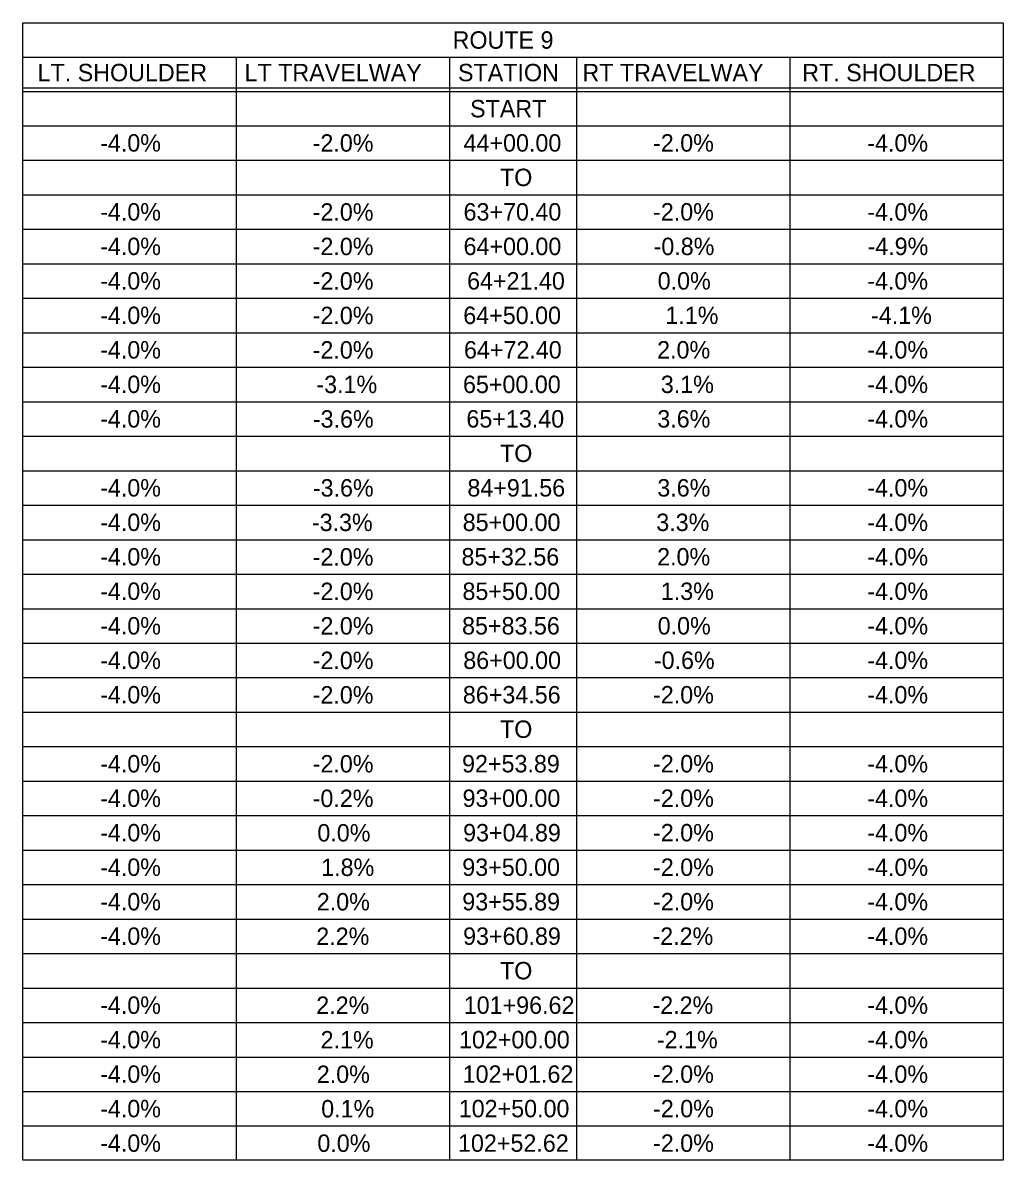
# Model space of a CAD drawing. Extents: x -15319374 to 1762012, y 465773 to 3693661.
# Drawn here: x -15318626.1 to -15318457.2, y 3691771.6 to 3691967.6 of the extents above; entities that cross this region are included whole.
import ezdxf

# ---------------------------------------------------------------- set-up
doc = ezdxf.new("R2010")
doc.units = 0
doc.layers.add('BORDER', color=7, linetype='Continuous')
doc.layers.add('DIMENSIONS', color=7, linetype='Continuous')

msp = doc.modelspace()

# ---------------------------------------------------------------- linework, layer by layer
at = {"layer": 'BORDER'}
for p, q in [((-15318589.38, 3691961.63), (-15318589.38, 3691771.58)), ((-15318552.61, 3691961.63), (-15318552.61, 3691771.58)), ((-15318530.73, 3691961.63), (-15318530.73, 3691771.58)), ((-15318493.97, 3691961.63), (-15318493.97, 3691771.58)), ((-15318626.15, 3691956.35), (-15318457.2, 3691956.35)), ((-15318626.15, 3691955.75), (-15318457.2, 3691955.75)), ((-15318626.15, 3691949.81), (-15318457.2, 3691949.81)), ((-15318626.15, 3691949.81), (-15318457.2, 3691949.81)), ((-15318626.15, 3691949.81), (-15318457.2, 3691949.81)), ((-15318626.15, 3691943.87), (-15318457.2, 3691943.87)), ((-15318626.15, 3691937.92), (-15318457.2, 3691937.92)), ((-15318626.15, 3691931.98), (-15318457.2, 3691931.98)), ((-15318626.15, 3691926.04), (-15318457.2, 3691926.04)), ((-15318626.15, 3691920.1), (-15318457.2, 3691920.1)), ((-15318626.15, 3691914.15), (-15318457.2, 3691914.15)), ((-15318626.15, 3691908.21), (-15318457.2, 3691908.21)), ((-15318626.15, 3691902.27), (-15318457.2, 3691902.27)), ((-15318626.15, 3691896.33), (-15318457.2, 3691896.33)), ((-15318626.15, 3691890.38), (-15318457.2, 3691890.38)), ((-15318626.15, 3691884.44), (-15318457.2, 3691884.44)), ((-15318626.15, 3691878.5), (-15318457.2, 3691878.5)), ((-15318626.15, 3691872.56), (-15318457.2, 3691872.56)), ((-15318626.15, 3691866.61), (-15318457.2, 3691866.61)), ((-15318626.15, 3691860.67), (-15318457.2, 3691860.67)), ((-15318626.15, 3691854.73), (-15318457.2, 3691854.73)), ((-15318626.15, 3691848.78), (-15318457.2, 3691848.78)), ((-15318626.15, 3691842.84), (-15318457.2, 3691842.84)), ((-15318626.15, 3691836.9), (-15318457.2, 3691836.9)), ((-15318626.15, 3691830.96), (-15318457.2, 3691830.96)), ((-15318626.15, 3691825.01), (-15318457.2, 3691825.01)), ((-15318626.15, 3691819.07), (-15318457.2, 3691819.07)), ((-15318626.15, 3691813.13), (-15318457.2, 3691813.13)), ((-15318626.15, 3691807.19), (-15318457.2, 3691807.19)), ((-15318626.15, 3691801.24), (-15318457.2, 3691801.24)), ((-15318626.15, 3691795.3), (-15318457.2, 3691795.3)), ((-15318626.15, 3691789.36), (-15318457.2, 3691789.36)), ((-15318626.15, 3691783.41), (-15318457.2, 3691783.41)), ((-15318626.15, 3691777.49), (-15318457.2, 3691777.49))]:
    msp.add_line(p, q, dxfattribs=at)
msp.add_lwpolyline([(-15318626.15, 3691961.63), (-15318626.15, 3691967.57), (-15318457.2, 3691967.57), (-15318457.2, 3691961.63)], dxfattribs=at)
msp.add_lwpolyline([(-15318626.15, 3691961.63), (-15318457.2, 3691961.63), (-15318457.2, 3691771.58), (-15318626.15, 3691771.58)], close=True, dxfattribs=at)

# ---------------------------------------------------------------- texts
at = {"layer": 'DIMENSIONS'}
for s, p in [('ROUTE 9', (-15318552.08, 3691963.1)), ('LT. SHOULDER', (-15318623.59, 3691957.49)), ('LT TRAVELWAY', (-15318587.93, 3691957.49)), ('STATION', (-15318551.15, 3691957.49)), ('RT TRAVELWAY', (-15318529.71, 3691957.49)), ('RT. SHOULDER', (-15318491.84, 3691957.49)), ('START', (-15318549.07, 3691951.27)), ('-4.0%', (-15318612.81, 3691945.37)), ('-2.0%', (-15318576.19, 3691945.36)), ('44+00.00', (-15318550.19, 3691945.37)), ('-2.0%', (-15318517.54, 3691945.37)), ('-4.0%', (-15318480.63, 3691945.37)), ('TO', (-15318543.91, 3691939.43)), ('-4.0%', (-15318612.81, 3691933.49)), ('-2.0%', (-15318576.19, 3691933.47)), ('63+70.40', (-15318550.19, 3691933.49)), ('-2.0%', (-15318517.54, 3691933.49)), ('-4.0%', (-15318480.63, 3691933.49)), ('-4.0%', (-15318612.81, 3691927.54)), ('-2.0%', (-15318576.19, 3691927.53)), ('64+00.00', (-15318550.19, 3691927.54)), ('-0.8%', (-15318517.45, 3691927.54)), ('-4.9%', (-15318480.59, 3691927.54)), ('-4.0%', (-15318612.81, 3691921.6)), ('-2.0%', (-15318576.19, 3691921.58)), ('64+21.40', (-15318549.58, 3691921.6)), ('0.0%', (-15318516.74, 3691921.6)), ('-4.0%', (-15318480.63, 3691921.6)), ('-4.0%', (-15318612.81, 3691915.66)), ('-2.0%', (-15318576.19, 3691915.64)), ('64+50.00', (-15318550.24, 3691915.66)), ('1.1%', (-15318515.42, 3691915.66)), ('-4.1%', (-15318479.97, 3691915.66)), ('-4.0%', (-15318612.81, 3691909.72)), ('-2.0%', (-15318576.19, 3691909.7)), ('64+72.40', (-15318550.12, 3691909.72)), ('2.0%', (-15318516.84, 3691909.72)), ('-4.0%', (-15318480.63, 3691909.72)), ('-4.0%', (-15318612.81, 3691903.77)), ('-3.1%', (-15318575.55, 3691903.76)), ('65+00.00', (-15318550.29, 3691903.77)), ('3.1%', (-15318516.2, 3691903.77)), ('-4.0%', (-15318480.63, 3691903.77)), ('-4.0%', (-15318612.81, 3691897.83)), ('-3.6%', (-15318576.16, 3691897.81)), ('65+13.40', (-15318549.7, 3691897.83)), ('3.6%', (-15318516.81, 3691897.83)), ('-4.0%', (-15318480.63, 3691897.83)), ('TO', (-15318543.91, 3691891.89)), ('-4.0%', (-15318612.81, 3691885.94)), ('-3.6%', (-15318576.16, 3691885.93)), ('84+91.56', (-15318549.53, 3691885.94)), ('3.6%', (-15318516.81, 3691885.94)), ('-4.0%', (-15318480.63, 3691885.94)), ('-4.0%', (-15318612.81, 3691880)), ('-3.3%', (-15318576.33, 3691879.99)), ('85+00.00', (-15318550.34, 3691880)), ('3.3%', (-15318516.98, 3691880)), ('-4.0%', (-15318480.63, 3691880)), ('-4.0%', (-15318612.81, 3691874.06)), ('-2.0%', (-15318576.19, 3691874.04)), ('85+32.56', (-15318550.55, 3691874.06)), ('2.0%', (-15318516.84, 3691874.06)), ('-4.0%', (-15318480.63, 3691874.06)), ('-4.0%', (-15318612.81, 3691868.12)), ('-2.0%', (-15318576.19, 3691868.1)), ('85+50.00', (-15318550.38, 3691868.12)), ('1.3%', (-15318516.2, 3691868.12)), ('-4.0%', (-15318480.63, 3691868.12)), ('-4.0%', (-15318612.81, 3691862.17)), ('-2.0%', (-15318576.19, 3691862.16)), ('85+83.56', (-15318550.45, 3691862.17)), ('0.0%', (-15318516.74, 3691862.17)), ('-4.0%', (-15318480.63, 3691862.17)), ('-4.0%', (-15318612.81, 3691856.23)), ('-2.0%', (-15318576.19, 3691856.21)), ('86+00.00', (-15318550.24, 3691856.23)), ('-0.6%', (-15318517.4, 3691856.23)), ('-4.0%', (-15318480.63, 3691856.23)), ('-4.0%', (-15318612.81, 3691850.29)), ('-2.0%', (-15318576.19, 3691850.27)), ('86+34.56', (-15318550.31, 3691850.29)), ('-2.0%', (-15318517.54, 3691850.29)), ('-4.0%', (-15318480.63, 3691850.29)), ('TO', (-15318543.91, 3691844.35)), ('-4.0%', (-15318612.81, 3691838.4)), ('-2.0%', (-15318576.19, 3691838.39)), ('92+53.89', (-15318550.45, 3691838.4)), ('-2.0%', (-15318517.54, 3691838.4)), ('-4.0%', (-15318480.63, 3691838.4)), ('-4.0%', (-15318612.81, 3691832.46)), ('-0.2%', (-15318576.19, 3691832.44)), ('93+00.00', (-15318550.36, 3691832.46)), ('-2.0%', (-15318517.54, 3691832.46)), ('-4.0%', (-15318480.63, 3691832.46)), ('-4.0%', (-15318612.81, 3691826.52)), ('0.0%', (-15318575.38, 3691826.5)), ('93+04.89', (-15318550.27, 3691826.52)), ('-2.0%', (-15318517.54, 3691826.52)), ('-4.0%', (-15318480.63, 3691826.52)), ('-4.0%', (-15318612.81, 3691820.57)), ('1.8%', (-15318574.72, 3691820.56)), ('93+50.00', (-15318550.41, 3691820.57)), ('-2.0%', (-15318517.54, 3691820.57)), ('-4.0%', (-15318480.63, 3691820.57)), ('-4.0%', (-15318612.81, 3691814.63)), ('2.0%', (-15318575.48, 3691814.62)), ('93+55.89', (-15318550.41, 3691814.63)), ('-2.0%', (-15318517.54, 3691814.63)), ('-4.0%', (-15318480.63, 3691814.63)), ('-4.0%', (-15318612.81, 3691808.69)), ('2.2%', (-15318575.57, 3691808.67)), ('93+60.89', (-15318550.27, 3691808.69)), ('-2.2%', (-15318517.64, 3691808.69)), ('-4.0%', (-15318480.63, 3691808.69)), ('TO', (-15318543.91, 3691802.75)), ('-4.0%', (-15318612.81, 3691796.8)), ('2.2%', (-15318575.57, 3691796.79)), ('101+96.62', (-15318550.16, 3691796.8)), ('-2.2%', (-15318517.64, 3691796.8)), ('-4.0%', (-15318480.63, 3691796.8)), ('-4.0%', (-15318612.81, 3691790.86)), ('2.1%', (-15318574.82, 3691790.84)), ('102+00.00', (-15318550.97, 3691790.86)), ('-2.1%', (-15318516.88, 3691790.86)), ('-4.0%', (-15318480.63, 3691790.86)), ('-4.0%', (-15318612.81, 3691784.92)), ('2.0%', (-15318575.48, 3691784.9)), ('102+01.62', (-15318550.35, 3691784.92)), ('-2.0%', (-15318517.54, 3691784.92)), ('-4.0%', (-15318480.63, 3691784.92)), ('-4.0%', (-15318612.81, 3691778.98)), ('0.1%', (-15318574.72, 3691778.96)), ('102+50.00', (-15318551.02, 3691778.98)), ('-2.0%', (-15318517.54, 3691778.98)), ('-4.0%', (-15318480.63, 3691778.98)), ('-4.0%', (-15318612.81, 3691773.03)), ('0.0%', (-15318575.38, 3691773.02)), ('102+52.62', (-15318551.15, 3691773.03)), ('-2.0%', (-15318517.54, 3691773.03)), ('-4.0%', (-15318480.63, 3691773.03))]:
    msp.add_text(s, height=3, dxfattribs=at).set_placement(p)

doc.saveas('drawing.dxf')
